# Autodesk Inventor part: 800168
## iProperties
Created: 2007-10
Part Number: 800168
Document SubType Name: Modeling
Designer: AL
Density: 8.08 g/cm^3
Mass: 16.5411 g
Surface Area: 16.0193 cm^2
Volume: 2.04717 cm^3
Material: Stainless Steel
Description: SCREW
Component Category: Fasteners
Author: AL
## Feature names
1. Revolution1
2. Extrusion1
3. Fillet1
4. Revolution2
